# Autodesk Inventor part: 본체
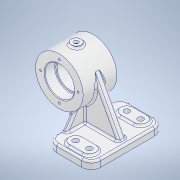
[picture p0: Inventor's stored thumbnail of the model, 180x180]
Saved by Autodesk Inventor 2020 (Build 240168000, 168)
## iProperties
Created: 2023-08
Part Number: 본체
Material: 알루미늄 6061
Document SubType Name: Modeling
Designer: oem
Density: 2.7 g/cm^3
Appearance: 알루미늄 - 평지
Mass: 777.812 g
Surface Area: 536.479 cm^2
Volume: 288.078 cm^3
Author: oem
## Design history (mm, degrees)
sketch "스케치1"
  geometry: L1 (20, -58)-(-20, -58); L2 (-35, -43)-(-35, 43); L3 (-20, 58)-(20, 58); L4 (35, 43)-(35, -43); L5 (35, -58)-(-35, 58); L6 (-35, -58)-(35, 58); A1 r 15 centre (20, -43) between (20, -58) and (35, -43); A2 r 15 centre (-20, -43) between (-35, -43) and (-20, -58); A3 r 15 centre (-20, 43) between (-20, 58) and (-35, 43); A4 r 15 centre (20, 43) between (35, 43) and (20, 58); 1 further point
  constraints: 12 end point, 8 point on circle, 8 point on line, 8 tangent, 4 centre point, 3 equal radius, 2 midpoint, 2 parallel, 1 horizontal, 1 perpendicular
  dimensions: "d0" = 70 distance of L5.end L6.end; "d1" = 116 distance of L6.start L5.end; "d2" = 15 radius of A1
extrude "돌출1" new body sketch "스케치1" distance "d3" = 12; taper "d4" = 0 deg
sketch "스케치2"
  geometry: L1 (-35, 43)-(-35, -43) reference; L2 (35, -43)-(35, 43) reference; L3 (-7, 41)-(15, 41); L4 (-7, 31)-(15, 31); L5 (15, 51)-(-7, 51); L6 (-35, 0)-(35, 0); L7 (-7, -31)-(15, -31); L8 (-7, -41)-(15, -41); L9 (15, -51)-(-7, -51); A1 r 15 centre (20, 43) between (35, 43) and (20, 58) reference; A2 r 10 centre (-7, 41) between (-7, 51) and (-7, 31); A3 r 10 centre (15, 41) between (15, 31) and (15, 51); A4 r 10 centre (-7, -41) between (-7, -31) and (-7, -51); A5 r 10 centre (15, -41) between (15, -51) and (15, -31); 4 further points
  constraints: 18 end point, 8 point on circle, 8 symmetric about line, 4 centre point, 4 tangent, 3 midpoint, 1 horizontal, 1 parallel, 2 other
  dimensions: "d6" = 11 distance of point (4, 41) L3.end; "d7" = 20 diameter of A3; "d8" = 41 vertical distance of point (0, 0) point (4, 41); "d9" = 20 distance from line of L2 L3.end
extrude "돌출2" join sketch "스케치2" distance "d10" = 3; taper "d11" = 0 deg
sketch "스케치3"
  geometry: L1 (-20, 0)-(-35, 0) reference; L2 (-35, 0)-(-35, 12) reference; L3 (-20, 12)-(-35, 12) reference; L4 (-20, 0)-(-20, 12) reference; L5 (20, 0)-(-20, 0) reference; L6 (-20, 0)-(-20, 12) reference; L7 (20, 12)-(-20, 12) reference; L8 (20, 0)-(20, 12) reference; L9 (35, 0)-(20, 0) reference; L10 (20, 0)-(20, 12) reference; L11 (35, 12)-(20, 12) reference; L12 (35, 0)-(35, 12) reference; C1 r 38 at (-47, 70); 1 further point
  constraints: 1 centre point
  dimensions: "d12" = 76 diameter of C1; "d13" = 70 distance from line of L1 C1.centre; "d14" = 82 distance from line of L12 C1.centre
extrude "돌출3" join sketch "스케치3" stored distance "d15" = 54; taper "d16" = 0 deg
sketch "스케치4"
  geometry: C1 r 38 at (0, 0) reference; C2 r 23.5 at (0, 0); 1 further point
  constraints: 1 centre point, 1 coincident
  dimensions: "d17" = 47 diameter of C2
extrude "돌출4" cut sketch "스케치4" distance "d18" = 17; taper "d19" = 0 deg
sketch "스케치5"
  geometry: C1 r 23.5 at (0, 0) reference; C2 r 20.5 at (0, 0); 1 further point
  constraints: 1 centre point, 1 coincident
  dimensions: "d20" = 41 diameter of C2
extrude "돌출5" cut sketch "스케치5" distance "d21" = 10; taper "d22" = 0 deg
sketch "스케치6"
  geometry: C1 r 23.5 at (0, 0) reference; 2 further points
  constraints: 1 vertical alignment
  dimensions: "d23" = 30 distance of C1.centre point (0, 30)
hole "구멍1" sketch "스케치6" at (0, 30) diameter "d24" = 3.242; stored, may be unused: countersink angle "d28" = 90 deg, drill point angle "d30" = 118 deg; dims "d25" = 8, "d26" = 4, "d27" = 2, "d29" = 10
fillet "모깎기1" dims "d34" = 1
chamfer "모따기1" distance "d35" = 1; stored, may be unused: second distance "d36" = 2, angle "d37" = 45 deg
sketch "스케치7"
  geometry: L1 (-7, -51)-(15, -51) reference; L2 (15, -31)-(-7, -31) reference; A1 r 10 centre (-7, 41) between (-7, 51) and (-7, 31) reference; A2 r 10 centre (15, 41) between (15, 31) and (15, 51) reference; A3 r 10 centre (-7, -41) between (-7, -31) and (-7, -51) reference; A4 r 10 centre (15, -41) between (15, -51) and (15, -31) reference; 1 further point
hole "구멍2" sketch "스케치7" at (-7, 41), (15, 41), (15, -41), (-7, -41) diameter "d38" = 9; stored, may be unused: countersink angle "d42" = 90 deg, drill point angle "d44" = 118 deg; dims "d39" = 8, "d40" = 4, "d41" = 2, "d43" = 10
node "작업 평면1"
sketch "스케치8"
  geometry: L1 (9, -27)-(85, -27) reference; L2 (85, 27)-(9, 27) reference; L3 (9, -27)-(9, 27) reference; C1 r 8 at (47, 0); 1 further point
  constraints: 1 centre point
  dimensions: "d46" = 16 diameter of C1; "d47" = 27 distance from line of L1 C1.centre; "d48" = 38 distance from line of L3 C1.centre
extrude "돌출6" join sketch "스케치8" distance "d49" = 3; taper "d51" = 0 deg; dims "d50" = 5, "d52" = 0
sketch "스케치9"
  geometry: C1 r 8 at (0, 0) reference; 1 further point
hole "구멍3" sketch "스케치9" at (0, 0) diameter "d53" = 5.1881; stored, may be unused: countersink angle "d57" = 90 deg, drill point angle "d59" = 118 deg; dims "d54" = 30, "d55" = 7, "d56" = 4, "d58" = 32
sketch "스케치11"
  geometry: L1 (-20, 0)-(-35, 0) reference; L2 (-35, 0)-(-35, 12) reference; L3 (-20, 12)-(-35, 12) reference; L4 (-20, 0)-(-20, 12) reference; L5 (20, 0)-(-20, 0) reference; L6 (-20, 0)-(-20, 12) reference; L7 (20, 12)-(-20, 12) reference; L8 (20, 0)-(20, 12) reference; L9 (35, 0)-(20, 0) reference; L10 (20, 0)-(20, 12) reference; L11 (35, 12)-(20, 12) reference; L12 (35, 0)-(35, 12) reference; L13 (35, 12)-(20, 12) reference; L14 (27, 12)-(-13.471, 87.882); L15 (-35, 0)-(-35, 12) reference; L16 (-35, 12)-(-35, 33.944); A1 r 38 centre (-47, 70) between (-13.471, 87.882) and (-35, 33.944) reference; 4 further points
  constraints: 4 end point, 2 point on circle, 1 point on line, 1 tangent, 1 vertical
  dimensions: "d61" = 8 distance of L11.start L14.start
extrude "돌출7" join sketch "스케치11" stored distance "d62" = 12; taper "d63" = 0 deg
sketch "스케치14"
  geometry: L1 (86, 0)-(86, 12) reference; L2 (49, 12)-(86, 12) reference; L3 (0, 12)-(37, 12) reference; L4 (0, 0)-(0, 12) reference; L5 (79, 12)-(60.817, 40); L6 (25.183, 40)-(7, 12); L7 (-15, 0)-(0, 0) reference; L8 (0, 0)-(0, 12) reference; L9 (-15, 12)-(0, 12) reference; L10 (-15, 0)-(-15, 12) reference; L11 (86, 0)-(101, 0) reference; L12 (101, 0)-(101, 12) reference; L13 (86, 12)-(101, 12) reference; L14 (86, 0)-(86, 12) reference; L15 (60.817, 40)-(25.183, 40); L16 (37, 12)-(49, 12) reference; L17 (37, 12)-(49, 12); 1 further point
  constraints: 8 end point, 2 point on line, 1 collinear
  dimensions: "d65" = 33 deg angle of L1 L5; "d66" = 33 deg angle of L4 L6; "d68" = 22 distance from line of L12 L5.start; "d69" = 22 distance from line of L10 L6.end; "d70" = 28 vertical distance of L5.start L5.end; "d71" = 28 vertical distance of L6.start L6.end
extrude "돌출8" join sketch "스케치14" distance "d72" = 8; taper "d73" = 0 deg
sketch "스케치15"
  geometry: L1 (0, 0)-(86, 0) reference; 3 further points
  constraints: 1 midpoint, 1 vertical alignment, 1 other
  dimensions: "d74" = 19 distance from line of L1 point (43, 19)
feature "엠보싱1" sketch "스케치15" dims "d0" = 70, "d1" = 116, "d2" = 15, "d75" = 0.5, "d76" = 0
fillet "모깎기2" dims "d77" = 3
fillet "모깎기3" dims "d78" = 3
node "솔리드1"
pattern_circular "원형 패턴1" dims angle "d32" = 360 deg
mirror "미러1"
node "투영된 루프1"
node "투영된 루프2"
node "투영된 루프3"
node "투영된 루프4"
node "투영된 루프5"
node "투영된 루프6"
node "투영된 루프7"
node "투영된 루프8"
node "투영된 루프14"
node "투영된 루프15"
feature "A9D066F2-1C7D-4E18-AEED-F7BC21143FA4" dims "d38" = 9, "d39" = 8, "d40" = 4, "d41" = 2, "d42" = 90 deg, "d43" = 10, "d44" = 118 deg
other parameters: "d45" = 108
